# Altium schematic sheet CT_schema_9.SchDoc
size 274 x 160 mm
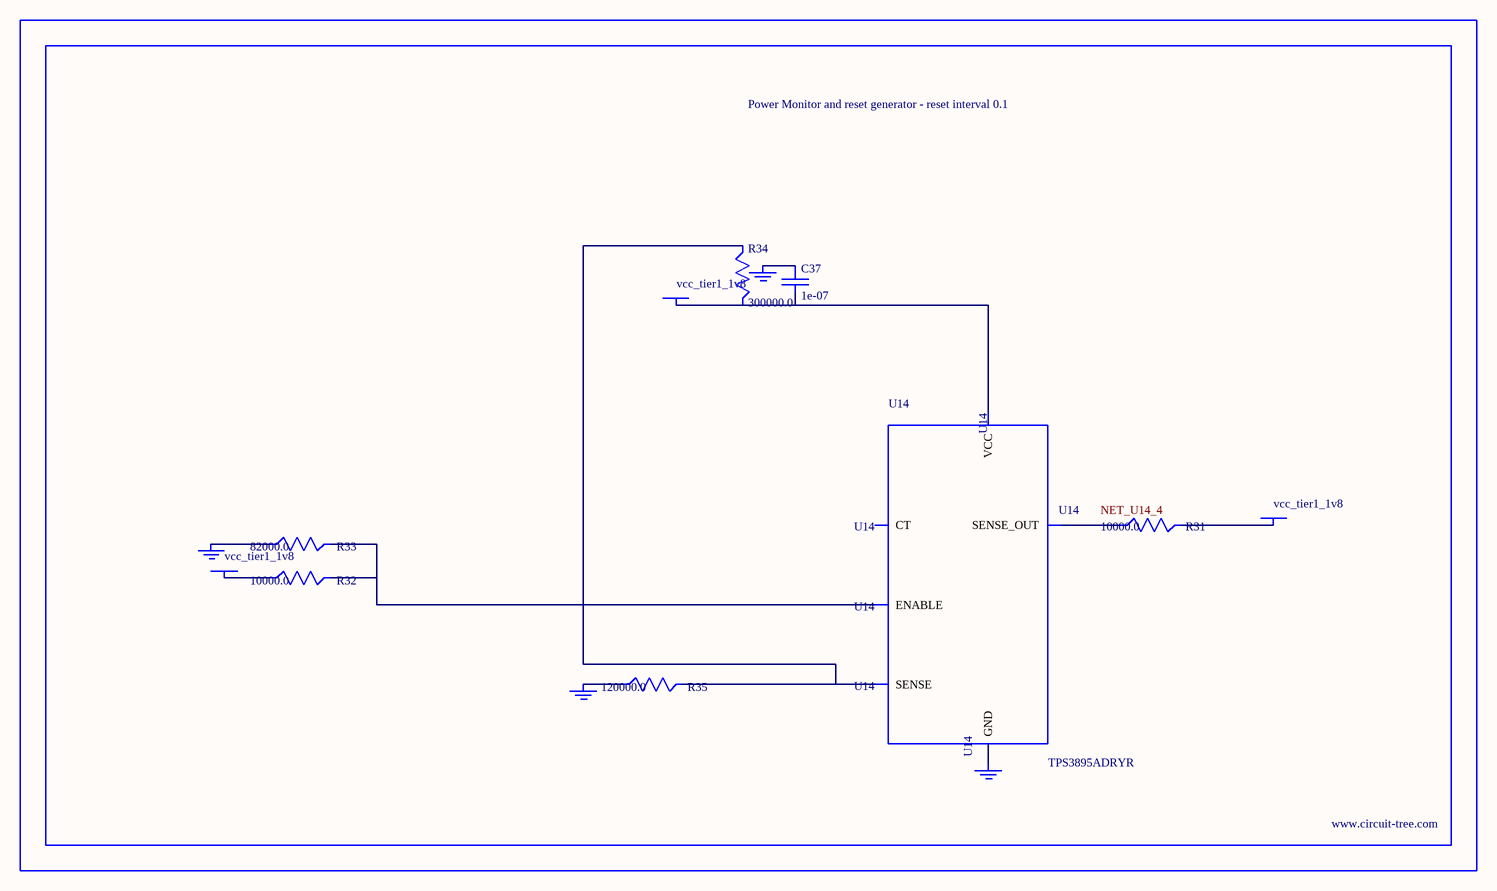
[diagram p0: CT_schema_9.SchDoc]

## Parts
BORDER8  (no value)
C37  1e-07  [C0402]
GND_INSTANCE_8_0  (no value)
GND_INSTANCE_8_1  (no value)
GND_INSTANCE_8_2  (no value)
GND_INSTANCE_8_3  (no value)
POWER_INSTANCE_8_0  vcc_tier1_1v8
POWER_INSTANCE_8_1  vcc_tier1_1v8
POWER_INSTANCE_8_2  vcc_tier1_1v8
R31  10000.0  [R0603]
R32  10000.0  [R0603]
R33  82000.0  [R0603]
R34  300000.0  [R0603]
R35  120000.0  [R0603]
U14  TPS3895ADRYR  [SON-6]

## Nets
NetC37_1: C37.1 GND_INSTANCE_8_2.0(GND)
NetC37_2: C37.2 POWER_INSTANCE_8_2.0(PWR) R34.2 U14.6(VCC)
NetGND_INSTANCE_8_0_0: GND_INSTANCE_8_0.0(GND) R33.1
NetGND_INSTANCE_8_1_0: GND_INSTANCE_8_1.0(GND) R35.1
NetGND_INSTANCE_8_3_0: GND_INSTANCE_8_3.0(GND) U14.2(GND)
NetPOWER_INSTANCE_8_0_0: POWER_INSTANCE_8_0.0(PWR) R32.1
NetPOWER_INSTANCE_8_1_0: POWER_INSTANCE_8_1.0(PWR) R31.2
NetR31_1: R31.1 U14.4(SENSE_OUT)
NetR32_2: R32.2 R33.2 U14.1(ENABLE)
NetR34_1: R34.1 R35.2 U14.3(SENSE)

Not connected (* = marked no-connect by the designer): U14 5(CT)

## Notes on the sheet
- Labels drawn without touching a wire or pin: NET_U14_4

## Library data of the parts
BORDER8 = BORDER_PAGE8
C37 = C0402C104K3RACTU
GND_INSTANCE_8_0-GND_INSTANCE_8_3 = GND
POWER_INSTANCE_8_0-POWER_INSTANCE_8_2 = PWR
R31 R32 = RC0603JR-0710KL
R33 = RC0603JR-0782KL
R34 = RC0603JR-07300KL
R35 = RC0603JR-07120KL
